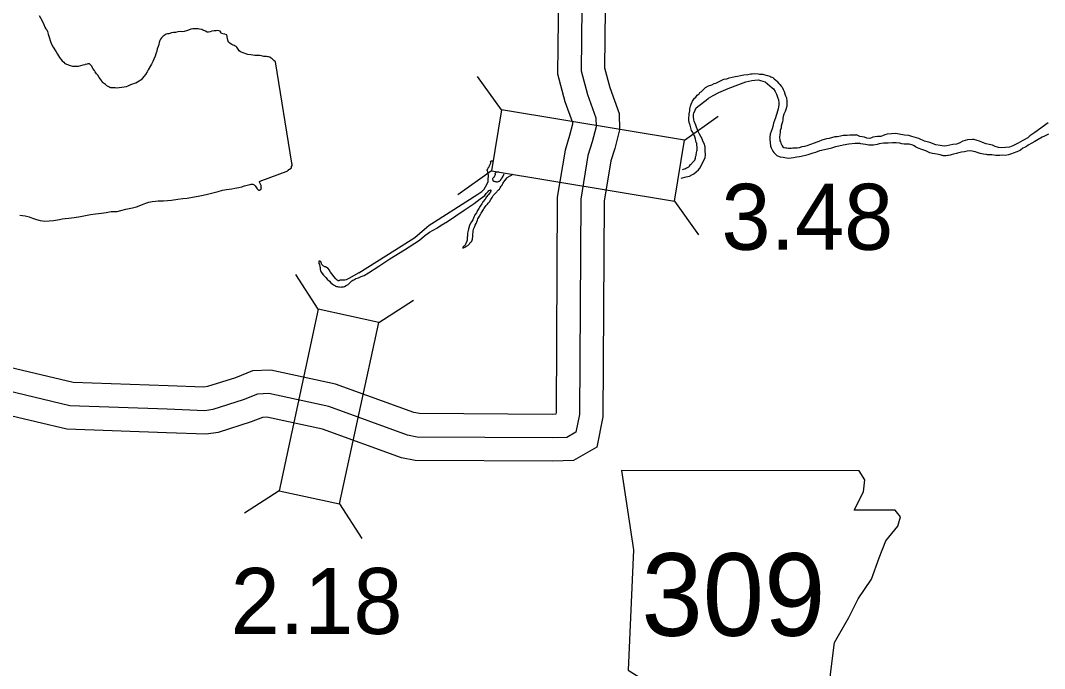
# Model space of a CAD drawing. Extents: x -83719 to 153526, y -11835 to 11446.
# Drawn here: x -4570.7 to -4352.2, y -30.4 to 107.8 of the extents above; entities that cross this region are included whole.
import ezdxf

# ---------------------------------------------------------------- set-up
doc = ezdxf.new("R2010")
doc.units = 0
for name, color, linetype in [('Level 10', 7, 'Continuous'), ('Level 20', 7, 'Continuous'), ('Level 21', 7, 'Continuous'), ('Level 25', 7, 'Continuous'), ('Level 58', 7, 'Continuous'), ('Level 59', 7, 'Continuous'), ('Level 9', 7, 'Continuous')]:
    doc.layers.add(name, color=color, linetype=linetype)

msp = doc.modelspace()

# ---------------------------------------------------------------- linework, layer by layer
at = {"layer": 'Level 10'}
for points in [[(-4455.75, 125.23), (-4456.06, 96.41), (-4454.48, 90.48), (-4452.86, 86.04), (-4452.85, 85.63), (-4453.48, 83.25), (-4454.45, 80.12), (-4456.11, 70.1), (-4456.37, 24.26), (-4456.46, 23.8), (-4457.21, 23.78), (-4485.53, 23.95), (-4486.75, 24.17), (-4503.46, 30.25), (-4517.26, 33.23), (-4521.18, 33.03), (-4524.8, 31.59), (-4530.76, 29.7), (-4531.56, 29.58), (-4539.13, 29.88), (-4559.44, 30.61), (-4572.91, 33.78)], [(-4445.78, 122.85), (-4446.05, 97.67), (-4444.93, 93.48), (-4442.91, 87.94), (-4442.82, 84.48), (-4443.86, 80.5), (-4444.69, 77.81), (-4446.11, 69.25), (-4446.37, 23.23), (-4447.68, 16.79), (-4452.68, 13.92), (-4457.08, 13.78), (-4486.46, 13.95), (-4489.38, 14.49), (-4506.24, 20.62), (-4518.07, 23.18), (-4519.02, 23.13), (-4521.43, 22.17), (-4528.49, 19.93), (-4531.01, 19.55), (-4539.51, 19.88), (-4560.78, 20.65), (-4573.96, 23.76)]]:
    msp.add_lwpolyline(points, dxfattribs=at)
at = {"layer": 'Level 20'}
for p, q in [((-4468.03, 88.71), (-4473.15, 95.86)), ((-4428.96, 82.25), (-4421.8, 87.37)), ((-4470.18, 75.68), (-4477.34, 70.56)), ((-4431.11, 69.22), (-4425.99, 62.07)), ((-4507.11, 46.18), (-4511.88, 53.58)), ((-4494.21, 43.39), (-4486.81, 48.16)), ((-4515.48, 7.47), (-4522.88, 2.71)), ((-4502.58, 4.68), (-4497.82, -2.71))]:
    msp.add_line(p, q, dxfattribs=at)
for points in [[(-4470.18, 75.68), (-4431.11, 69.22), (-4428.96, 82.25), (-4468.03, 88.71)], [(-4507.11, 46.18), (-4515.48, 7.47), (-4502.58, 4.68), (-4494.21, 43.39)]]:
    msp.add_lwpolyline(points, close=True, dxfattribs=at)
at = {"layer": 'Level 21'}
msp.add_lwpolyline([(-4442.39, 11.79), (-4439.85, -5.12), (-4440.98, -30.78), (-4438.73, -32.19), (-4434.5, -32.19), (-4434.5, -41.21), (-4398.97, -41.21), (-4397.28, -37.55), (-4397.84, -31.63), (-4396.99, -24.86), (-4393.89, -19.5), (-4391.92, -15.56), (-4389.1, -11.33), (-4387.41, -6.82), (-4386, -3.15), (-4383.46, -0.05), (-4382.9, 1.93), (-4384.02, 3.34), (-4392.77, 3.34), (-4390.79, 7.28), (-4390.51, 9.82), (-4391.68, 11.77)], close=True, dxfattribs=at)
at = {"layer": 'Level 59'}
msp.add_lwpolyline([(-4450.76, 124.04), (-4451.05, 97.04), (-4449.7, 91.98), (-4447.89, 86.99), (-4447.83, 85.06), (-4448.67, 81.88), (-4449.57, 78.97), (-4451.11, 69.67), (-4451.37, 23.74), (-4452.13, 20), (-4454.08, 18.88), (-4457.15, 18.78), (-4486, 18.95), (-4488.06, 19.33), (-4504.85, 25.43), (-4517.67, 28.2), (-4520.1, 28.08), (-4523.12, 26.88), (-4529.62, 24.81), (-4531.29, 24.56), (-4539.32, 24.88), (-4560.11, 25.63), (-4573.43, 28.77)], dxfattribs=at)
at = {"layer": 'Level 9'}
for points in [[(-4566.66, 108.87), (-4566.05, 107.71), (-4565.64, 106.95), (-4565.47, 106.38), (-4565.23, 106.02), (-4565.03, 105.75), (-4564.89, 105.45), (-4564.72, 104.82), (-4564.51, 104.22), (-4564.27, 103.32), (-4564, 102.69), (-4563.69, 102.06), (-4563.05, 101.1), (-4562.74, 100.6), (-4562.34, 99.91), (-4561.73, 99.18), (-4561.43, 98.85), (-4561.16, 98.58), (-4560.05, 98.19), (-4559.55, 98.06), (-4558.69, 98.01), (-4558.29, 98.04), (-4557.79, 98.15), (-4557.26, 98.29), (-4556.86, 98.39), (-4556.76, 98.43), (-4556.36, 98.5)], [(-4528.08, 105.46), (-4528.32, 105.59), (-4528.59, 105.62), (-4528.89, 105.59), (-4529.35, 105.55), (-4529.82, 105.48), (-4530.18, 105.37), (-4530.51, 105.27), (-4530.65, 105.27), (-4530.81, 105.3), (-4531.18, 105.5), (-4531.32, 105.56), (-4531.75, 105.73), (-4531.99, 105.86), (-4532.49, 105.92), (-4532.72, 105.98), (-4533.05, 105.98), (-4533.49, 105.97), (-4533.85, 106), (-4534.32, 105.93), (-4534.78, 105.69), (-4535.21, 105.59), (-4535.75, 105.42), (-4536.11, 105.38), (-4536.61, 105.41), (-4537.08, 105.37), (-4537.61, 105.23), (-4537.78, 105.23), (-4538.01, 105.23), (-4538.44, 105.16), (-4538.97, 104.95), (-4539.27, 104.91), (-4539.6, 104.84), (-4539.8, 104.71), (-4540.03, 104.54), (-4540.23, 104.4), (-4540.53, 104.07), (-4540.76, 103.8), (-4540.89, 103.53), (-4541.05, 103.06), (-4541.15, 102.66), (-4541.24, 102.19), (-4541.47, 101.72), (-4541.57, 101.25), (-4541.76, 100.65), (-4541.92, 100.15), (-4542.18, 99.54), (-4542.38, 99.04), (-4542.67, 98.47), (-4542.9, 98.07), (-4543.42, 97.26), (-4543.65, 96.79), (-4544.01, 96.22), (-4544.34, 95.82), (-4544.6, 95.45), (-4544.9, 95.14), (-4545.33, 94.81), (-4545.69, 94.6), (-4546.03, 94.43), (-4546.39, 94.33), (-4546.76, 94.16), (-4547.15, 94.02), (-4547.45, 93.92), (-4547.65, 93.81), (-4547.75, 93.78)], [(-4519.64, 71.61), (-4519.41, 71.71), (-4519.35, 71.74), (-4519.25, 71.98), (-4519.28, 72.18), (-4519.32, 72.24), (-4519.29, 72.48), (-4519.32, 72.58), (-4519.42, 72.84), (-4519.49, 72.98), (-4519.66, 73.27), (-4519.63, 73.41), (-4519.2, 73.65), (-4519.17, 73.65), (-4513.96, 75.57), (-4513.76, 75.67), (-4513.56, 75.84), (-4513.49, 75.87), (-4513.36, 75.98), (-4513.23, 76.08), (-4512.93, 76.25), (-4512.83, 76.52), (-4512.8, 76.62), (-4512.7, 76.88), (-4512.71, 77.08), (-4512.74, 77.25), (-4512.77, 77.32), (-4512.77, 77.38), (-4516.26, 98.98), (-4516.63, 99.27), (-4516.66, 99.34), (-4516.9, 99.54), (-4516.9, 99.57), (-4517, 99.64), (-4517.13, 99.73), (-4517.27, 99.87), (-4517.37, 99.9), (-4517.44, 99.93), (-4517.7, 100), (-4517.87, 100.03), (-4518.14, 100.06), (-4518.74, 100.12), (-4519.24, 100.21), (-4519.6, 100.28), (-4520.1, 100.27), (-4520.44, 100.3), (-4520.67, 100.33), (-4521.07, 100.36), (-4521.47, 100.42), (-4522.14, 100.55), (-4522.57, 100.68), (-4522.91, 100.78), (-4523.38, 100.94), (-4523.74, 101.07), (-4524.01, 101.33), (-4524.22, 101.66), (-4524.52, 102.06), (-4524.62, 102.19), (-4524.86, 102.32), (-4525.06, 102.42), (-4525.29, 102.52), (-4525.59, 102.62), (-4525.93, 102.88), (-4526.26, 103.18), (-4526.43, 103.61), (-4526.47, 103.91), (-4526.64, 104.68), (-4526.71, 104.74), (-4527.05, 104.87), (-4527.15, 104.87), (-4527.51, 104.93), (-4527.78, 105.03), (-4527.85, 105.16), (-4528.08, 105.46)], [(-4556.01, 98.51), (-4556.36, 98.5)], [(-4554.88, 97.08), (-4555.18, 97.51), (-4555.32, 97.71), (-4555.46, 98.01), (-4555.66, 98.24), (-4555.86, 98.47), (-4555.96, 98.5), (-4556.01, 98.51)], [(-4553.36, 94.99), (-4553.58, 95.23), (-4553.83, 95.61), (-4554.15, 96.11), (-4554.45, 96.43), (-4554.7, 96.8), (-4554.88, 97.08)], [(-4420.57, 95.24), (-4419.97, 95.35), (-4419.44, 95.53), (-4418.78, 95.71), (-4418.15, 95.82), (-4417.69, 95.93), (-4417.05, 96.04), (-4416.29, 96.19), (-4415.49, 96.28), (-4415.16, 96.35), (-4414.83, 96.39), (-4414.53, 96.43), (-4413.97, 96.44), (-4413.23, 96.39), (-4412.96, 96.36), (-4412.27, 96.34), (-4411.83, 96.21), (-4411.26, 96.06), (-4410.79, 95.87), (-4410.52, 95.74), (-4410.15, 95.58), (-4409.85, 95.35), (-4409.51, 95.03), (-4409.24, 94.83), (-4408.86, 94.34), (-4408.66, 94.11), (-4408.35, 93.78), (-4408.11, 93.52), (-4407.91, 93.09), (-4407.73, 92.63), (-4407.55, 92.13), (-4407.45, 91.73), (-4407.2, 91.3), (-4407.12, 90.57), (-4407.11, 89.94), (-4407.17, 89.47), (-4407.35, 88.8), (-4407.48, 88.39), (-4407.77, 87.79), (-4407.89, 87.32), (-4407.98, 86.95), (-4407.98, 86.62), (-4408.04, 86.15), (-4408.19, 85.71), (-4408.32, 85.21), (-4408.38, 84.91), (-4408.44, 84.7), (-4408.53, 84.3), (-4408.59, 83.97), (-4408.65, 83.4), (-4408.67, 82.93), (-4408.62, 82.13), (-4408.52, 81.93), (-4408.41, 81.64), (-4408.31, 81.3), (-4408.13, 81.04), (-4408, 80.84), (-4407.76, 80.71), (-4407.33, 80.62), (-4407.13, 80.59), (-4406.76, 80.57), (-4406.39, 80.57), (-4406.23, 80.58), (-4405.86, 80.59), (-4405.63, 80.59), (-4404.96, 80.6), (-4404.47, 80.71), (-4403.87, 80.89), (-4403.31, 81), (-4402.81, 81.11), (-4402.05, 81.4), (-4401.22, 81.68), (-4400.66, 81.92), (-4400.23, 82.07), (-4399.57, 82.31), (-4398.57, 82.6), (-4398.01, 82.71), (-4396.85, 83), (-4396.35, 83.04), (-4395.66, 83.19), (-4395.09, 83.3), (-4394.26, 83.35), (-4393.69, 83.4), (-4393.3, 83.4), (-4392.73, 83.38), (-4392.56, 83.39), (-4392.36, 83.41)], [(-4550.94, 93.41), (-4551.34, 93.44), (-4551.58, 93.51), (-4551.81, 93.6), (-4552.22, 93.87), (-4552.52, 94.1), (-4552.75, 94.23), (-4552.95, 94.43), (-4553.09, 94.56), (-4553.29, 94.86), (-4553.36, 94.99)], [(-4429.39, 76.03), (-4428.79, 76.19), (-4428.56, 76.33), (-4428.33, 76.43), (-4428.06, 76.54), (-4427.93, 76.71), (-4427.67, 77.05), (-4427.57, 77.15), (-4427.44, 77.25), (-4427.35, 77.39), (-4427.02, 77.73), (-4426.95, 77.8), (-4426.79, 78), (-4426.6, 78.4), (-4426.6, 78.67), (-4426.51, 78.97), (-4426.51, 79.17), (-4426.42, 79.47), (-4426.39, 79.64), (-4426.36, 79.88), (-4426.27, 80.11), (-4426.24, 80.41), (-4426.24, 80.61), (-4426.25, 80.81), (-4426.32, 81.21), (-4426.36, 81.61), (-4426.47, 81.78), (-4426.54, 82.18), (-4426.61, 82.44), (-4426.76, 82.97), (-4426.79, 83.1), (-4426.96, 83.37), (-4427.14, 83.73), (-4427.28, 84), (-4427.45, 84.33), (-4427.63, 84.86), (-4427.77, 85.42), (-4427.95, 86.05), (-4428.02, 86.55), (-4428.06, 86.85), (-4427.98, 87.69), (-4427.98, 87.89), (-4427.86, 88.52), (-4427.84, 88.96), (-4427.68, 89.53), (-4427.53, 89.96), (-4427.24, 90.57), (-4426.95, 91.01), (-4426.82, 91.21), (-4426.59, 91.45), (-4426.26, 91.82), (-4425.87, 92.16), (-4425.68, 92.4), (-4425.41, 92.57), (-4425.09, 92.91), (-4424.82, 93.12), (-4424.46, 93.46), (-4423.87, 93.84), (-4423.14, 94.05), (-4422.65, 94.3), (-4422.29, 94.44), (-4421.69, 94.72), (-4421.16, 94.96), (-4420.57, 95.24)], [(-4425.04, 82.07), (-4425.22, 82.54), (-4425.52, 83.03), (-4425.8, 83.56), (-4426.04, 84.09), (-4426.43, 85.01), (-4426.57, 85.48), (-4426.89, 86.31), (-4426.96, 86.57), (-4427.07, 87.2), (-4427.08, 87.7), (-4426.96, 88.04), (-4426.73, 88.68), (-4426.48, 89.12), (-4424.9, 90.35), (-4424.34, 90.79), (-4423.85, 91.2), (-4422.83, 91.79), (-4421.65, 92.38), (-4419.66, 93.26), (-4417.61, 94.03), (-4415.86, 94.67), (-4414.6, 94.96), (-4413.94, 95.04), (-4413.21, 95.09), (-4412.74, 95), (-4411.77, 94.68), (-4411.26, 94.26), (-4410.78, 93.83), (-4410.24, 93.44), (-4409.97, 93.18), (-4409.63, 92.66), (-4409.32, 92.06), (-4409.14, 91.43), (-4408.93, 90.83), (-4408.82, 90.27), (-4408.84, 89.7), (-4408.9, 89.33), (-4408.99, 88.93), (-4409.15, 88.46), (-4409.27, 87.96), (-4409.43, 87.49), (-4409.55, 87.02), (-4409.96, 85.88), (-4410.15, 85.17), (-4410.3, 84.67), (-4410.72, 83.56), (-4410.77, 82.92), (-4410.79, 82.39), (-4410.71, 81.72), (-4410.63, 80.96), (-4410.49, 80.63), (-4410.14, 79.9), (-4409.94, 79.64), (-4409.57, 79.28), (-4409.29, 78.98), (-4409.16, 78.88), (-4408.59, 78.73), (-4407.92, 78.61), (-4407.22, 78.49), (-4406.88, 78.43), (-4406.22, 78.48), (-4405.72, 78.55), (-4405.02, 78.67), (-4404.43, 78.78), (-4403.43, 79), (-4402.57, 79.22), (-4401.51, 79.54), (-4400.98, 79.71), (-4400.12, 80.03), (-4399.13, 80.29), (-4397.57, 80.62), (-4396.71, 80.87), (-4395.12, 81.23), (-4393.92, 81.46), (-4392.56, 81.62), (-4391.69, 81.6)], [(-4547.75, 93.78), (-4548.07, 93.64), (-4548.54, 93.56), (-4549.06, 93.48), (-4549.58, 93.38), (-4550.15, 93.31), (-4550.47, 93.38), (-4550.94, 93.41)], [(-4351.37, 85.98), (-4354.22, 83.87), (-4355.28, 83.16), (-4355.74, 82.76), (-4356.8, 82.18), (-4357.76, 81.6), (-4358.93, 81.05), (-4359.62, 80.77), (-4361.32, 80.62), (-4361.99, 80.71), (-4362.66, 80.87), (-4363.27, 81.2), (-4364, 81.32), (-4364.6, 81.48), (-4365.38, 81.74), (-4366.05, 82.03), (-4366.52, 82.19), (-4367.22, 82.38), (-4367.52, 82.38), (-4368.62, 82.33), (-4369.58, 82.02), (-4370.38, 81.64), (-4370.95, 81.4), (-4371.75, 81.33), (-4373.01, 81.01), (-4373.58, 80.94), (-4374.45, 81.09), (-4375.38, 81.28), (-4376.62, 81.73), (-4377.8, 82.05), (-4378.94, 82.64), (-4380.44, 83.05), (-4381.11, 83.25), (-4382.05, 83.34), (-4383.19, 83.52), (-4383.86, 83.65), (-4384.82, 83.6), (-4385.72, 83.52), (-4386.22, 83.42), (-4386.75, 83.14), (-4387.05, 83.04), (-4387.79, 83.03), (-4388.29, 82.96), (-4388.79, 82.92), (-4389.05, 82.78)], [(-4389.05, 82.78), (-4389.45, 82.63), (-4390.07, 82.66), (-4390.54, 82.86), (-4391.56, 83.03), (-4392.13, 83.32), (-4392.36, 83.41)], [(-4351.34, 83.51), (-4352.17, 83.13), (-4352.67, 82.86), (-4353.53, 82.42), (-4354.23, 81.97), (-4354.86, 81.63), (-4355.66, 81.19), (-4356.02, 80.88), (-4356.42, 80.68), (-4356.75, 80.51), (-4357.25, 80.13), (-4357.68, 79.9), (-4358.04, 79.76), (-4358.84, 79.45), (-4359.21, 79.31), (-4359.87, 79.1), (-4360.47, 78.96), (-4361.14, 79.02), (-4361.71, 78.98), (-4362.57, 79), (-4363.38, 79.09), (-4363.78, 79.12), (-4364.31, 79.15), (-4364.51, 79.21), (-4365.18, 79.3), (-4365.52, 79.37), (-4365.92, 79.39), (-4366.28, 79.52), (-4366.55, 79.65), (-4366.89, 79.75), (-4367.02, 79.75), (-4367.62, 79.91), (-4367.96, 79.97), (-4368.63, 79.9), (-4369.23, 79.79), (-4369.86, 79.71), (-4370.19, 79.61), (-4370.69, 79.47), (-4370.96, 79.43), (-4371.59, 79.26), (-4372.09, 79.09), (-4372.32, 79.02), (-4372.62, 79.01), (-4372.69, 78.98), (-4372.82, 78.98), (-4373.12, 78.94), (-4373.25, 78.94), (-4373.35, 78.9), (-4373.59, 78.93), (-4373.69, 78.93), (-4373.96, 78.96), (-4374.02, 79), (-4374.42, 79.09), (-4374.42, 79.12), (-4374.79, 79.19), (-4375.56, 79.34), (-4376.06, 79.44), (-4376.33, 79.47), (-4376.63, 79.53), (-4377.51, 79.99), (-4378.31, 80.28), (-4379.15, 80.53), (-4379.72, 80.83), (-4379.95, 81.06), (-4380.26, 81.19), (-4380.72, 81.32), (-4381.03, 81.38), (-4382.09, 81.43), (-4382.6, 81.49), (-4383.03, 81.62), (-4383.8, 81.71), (-4384.57, 81.67), (-4385.5, 81.59), (-4385.94, 81.62), (-4386.54, 81.58), (-4387.46, 81.45)], [(-4429.72, 74.14), (-4428.65, 74.43), (-4427.92, 74.61), (-4427.3, 74.92), (-4426.97, 75.09), (-4426.02, 75.91), (-4425.69, 76.29), (-4424.82, 77.91), (-4424.54, 78.54), (-4424.52, 79.11), (-4424.57, 80.08), (-4424.58, 80.61), (-4424.58, 80.81), (-4424.8, 81.51), (-4425.04, 82.07)], [(-4387.46, 81.45), (-4387.86, 81.31), (-4388.62, 81.21), (-4389.61, 81.21), (-4390.37, 81.31), (-4391.33, 81.5), (-4391.69, 81.6)], [(-4498.45, 53.98), (-4490.79, 58.81), (-4486.51, 61.49), (-4483.92, 63.71), (-4483.43, 64.16), (-4482.31, 64.85), (-4473.07, 70.77), (-4472.22, 71.32), (-4471.73, 71.8), (-4471.4, 72.31), (-4470.89, 73.35), (-4470.87, 73.68), (-4470.84, 74.09), (-4470.81, 74.42), (-4470.79, 74.82), (-4470.83, 75.12), (-4470.9, 75.42), (-4470.93, 75.52), (-4471, 75.62), (-4471.04, 75.68), (-4471.07, 75.78), (-4471.11, 75.85), (-4471.11, 75.88), (-4471.08, 75.98), (-4471.04, 76.02), (-4470.95, 76.15), (-4470.88, 76.25), (-4470.85, 76.32), (-4470.79, 76.42), (-4470.75, 76.49), (-4470.66, 76.56), (-4470.66, 76.62), (-4470.56, 76.79), (-4470.5, 76.96), (-4470.43, 77.1), (-4470.4, 77.2), (-4470.31, 77.43), (-4470.31, 77.53), (-4470.34, 77.67), (-4470.31, 77.77), (-4470.25, 77.8), (-4470.18, 77.84), (-4470.15, 77.84), (-4470.12, 77.87), (-4469.95, 77.84), (-4469.9, 77.83)], [(-4470.61, 69.12), (-4470.32, 69.59), (-4470.03, 70.03), (-4469.96, 70.17), (-4469.77, 70.47), (-4469.51, 70.74), (-4469.28, 70.95), (-4469.05, 71.22), (-4468.92, 71.35), (-4468.86, 71.42), (-4468.66, 71.69), (-4468.46, 71.8), (-4468.3, 72.07), (-4468.08, 72.41), (-4467.91, 72.64), (-4467.79, 72.84), (-4467.72, 72.98), (-4467.59, 73.22), (-4467.53, 73.35), (-4467.24, 73.69), (-4467.2, 73.72), (-4467.14, 73.76), (-4466.91, 74.16), (-4466.81, 74.3), (-4465.56, 74.97)], [(-4469.36, 75.03), (-4469.36, 75.02), (-4469.36, 74.85), (-4469.48, 74.58), (-4469.48, 74.55), (-4469.55, 74.41), (-4469.58, 74.34), (-4469.71, 74.27), (-4469.81, 74.21), (-4469.87, 74.1), (-4469.91, 74.04), (-4469.94, 73.97), (-4469.94, 73.9), (-4469.9, 73.8), (-4469.9, 73.74), (-4469.87, 73.69)], [(-4469.36, 75.03), (-4469.35, 75.13), (-4469.33, 75.23), (-4469.3, 75.29), (-4469.16, 75.41), (-4468.99, 75.47), (-4468.87, 75.5), (-4468.69, 75.58), (-4468.65, 75.6)], [(-4468.13, 73.83), (-4468.08, 74.04), (-4467.91, 74.24), (-4467.69, 74.58), (-4467.49, 74.92), (-4467.45, 75.09)], [(-4531.69, 70.55), (-4530.76, 70.76), (-4528.47, 71.32), (-4527.57, 71.56), (-4526.67, 71.7), (-4525.54, 71.88), (-4524.91, 72.02), (-4524.05, 72.19), (-4523.45, 72.33), (-4522.82, 72.51), (-4522.29, 72.65), (-4521.99, 72.72), (-4521.62, 72.82), (-4521.42, 72.86), (-4521.26, 72.89), (-4521.09, 72.89), (-4520.79, 72.7), (-4520.59, 72.53), (-4520.56, 72.48)], [(-4520.56, 72.48), (-4520.46, 72.3), (-4520.29, 72.12), (-4520.14, 71.85), (-4519.96, 71.65), (-4519.85, 71.6), (-4519.64, 71.61)], [(-4469.87, 73.69), (-4469.84, 73.65), (-4469.78, 73.6), (-4469.71, 73.54), (-4469.6, 73.5)], [(-4469.6, 73.5), (-4469.43, 73.45), (-4469.26, 73.42), (-4469.09, 73.39), (-4468.99, 73.39), (-4468.9, 73.39), (-4468.64, 73.42)], [(-4468.13, 73.83), (-4468.16, 73.77), (-4468.21, 73.7), (-4468.29, 73.62), (-4468.43, 73.5), (-4468.54, 73.45), (-4468.64, 73.42)], [(-4570.79, 66.24), (-4570.25, 66.18), (-4569.68, 66.09), (-4568.82, 65.9), (-4568.08, 65.64), (-4567.24, 65.31), (-4566.48, 65.12), (-4565.48, 65), (-4564.54, 65.04), (-4563.58, 65.11), (-4562.35, 65.33), (-4561.78, 65.47), (-4561.09, 65.54), (-4560.32, 65.62), (-4559.22, 65.76), (-4557.86, 66.01), (-4556.76, 66.22), (-4555.7, 66.43), (-4554.67, 66.57), (-4553.37, 66.72), (-4552.34, 66.83), (-4551.27, 67.04), (-4550.04, 67.02), (-4549.24, 67.23), (-4548.15, 67.51), (-4546.72, 67.79), (-4545.92, 68.07), (-4545.32, 68.24), (-4544.46, 68.58), (-4543.7, 68.92), (-4543.3, 69.06), (-4542.54, 69.17), (-4541.84, 69.21), (-4541.3, 69.28), (-4540.14, 69.33), (-4539.27, 69.4), (-4538.44, 69.48), (-4537.11, 69.69), (-4535.98, 69.84), (-4535.08, 69.91), (-4533.92, 70.12), (-4532.75, 70.3), (-4531.69, 70.55)], [(-4484.42, 61.87), (-4483.37, 62.62), (-4481.82, 63.46), (-4480.9, 64.11), (-4479.55, 64.94), (-4475.97, 67.34), (-4473.83, 68.75), (-4472.55, 69.71), (-4471.57, 70.47), (-4471.28, 70.87), (-4471.08, 71.08), (-4470.89, 71.28), (-4470.69, 71.49), (-4470.66, 71.49), (-4470.52, 71.59), (-4470.43, 71.62), (-4470.39, 71.63), (-4470.36, 71.63), (-4470.29, 71.59), (-4470.29, 71.56), (-4470.29, 71.53), (-4470.29, 71.39), (-4470.35, 71.29), (-4470.38, 71.19), (-4470.48, 70.99), (-4470.77, 70.68), (-4470.94, 70.51), (-4471.2, 70.14), (-4471.52, 69.67), (-4471.97, 69.09), (-4472.23, 68.65), (-4472.59, 68.18), (-4472.88, 67.71), (-4473.17, 67.23), (-4473.36, 66.79), (-4473.69, 66.35), (-4473.78, 66.12), (-4473.91, 65.82), (-4474.16, 65.24), (-4474.42, 64.84), (-4474.62, 64.53), (-4474.87, 64.06), (-4474.96, 63.59), (-4475.06, 63.32), (-4475.12, 62.99), (-4475.21, 62.72), (-4475.27, 62.39), (-4475.3, 62.15), (-4475.3, 61.88), (-4475.29, 61.75), (-4475.32, 61.55), (-4475.32, 61.28), (-4475.38, 60.95), (-4475.41, 60.68), (-4475.53, 60.35), (-4475.63, 60.18), (-4475.73, 60.04), (-4475.85, 59.81), (-4475.95, 59.7), (-4476.08, 59.63), (-4476.22, 59.5), (-4476.25, 59.4), (-4476.25, 59.36), (-4476.28, 59.23), (-4476.14, 59.3), (-4475.82, 59.47), (-4475.62, 59.61), (-4475.49, 59.65), (-4475.19, 59.82), (-4475.06, 59.95), (-4474.86, 60.16), (-4474.67, 60.4), (-4474.5, 60.57), (-4474.37, 60.74), (-4474.28, 60.9), (-4474.18, 61.14), (-4474.19, 61.41), (-4474.16, 61.54), (-4474.13, 62.01), (-4474.14, 62.31), (-4474.08, 62.58), (-4474.05, 62.88), (-4473.96, 63.25), (-4473.8, 63.72), (-4473.64, 64.12), (-4473.45, 64.49), (-4473.29, 64.86), (-4473.16, 65.2), (-4473.04, 65.5), (-4472.91, 65.7), (-4472.71, 66.07), (-4472.46, 66.51), (-4472.33, 66.68), (-4471.88, 67.46), (-4471.78, 67.59), (-4471.68, 67.8), (-4471.52, 68.03), (-4471.29, 68.34), (-4471, 68.61), (-4470.84, 68.81), (-4470.61, 69.12)], [(-4499.72, 52.42), (-4499.56, 52.49), (-4499.09, 52.74), (-4498.8, 52.81), (-4498.56, 52.88), (-4497.94, 53.19), (-4497.34, 53.4), (-4496.39, 53.99), (-4494.22, 55.37), (-4491.82, 56.95), (-4488.69, 58.85), (-4485.53, 60.91), (-4484.42, 61.87)], [(-4506.86, 56.48), (-4506.89, 56.5), (-4506.95, 56.48), (-4506.98, 56.45), (-4507, 56.39), (-4507.01, 56.3), (-4507.01, 56.18), (-4506.99, 56.12)], [(-4506.99, 56.12), (-4506.99, 56.05), (-4506.98, 55.95), (-4506.88, 55.72), (-4506.84, 55.62), (-4506.81, 55.48), (-4506.8, 55.32), (-4506.73, 55.12), (-4506.73, 54.99), (-4506.69, 54.72), (-4506.69, 54.65), (-4506.66, 54.55), (-4506.62, 54.42), (-4506.55, 54.32), (-4506.55, 54.22), (-4506.51, 54.12), (-4505.97, 53.5), (-4505.53, 52.97), (-4505.25, 52.61), (-4504.74, 52.16), (-4504.41, 51.86), (-4504.13, 51.63), (-4503.97, 51.47), (-4503.76, 51.34), (-4503.7, 51.31), (-4503.59, 51.24), (-4503.43, 51.15), (-4503.36, 51.12), (-4503.22, 51.05), (-4503.12, 51.02), (-4502.99, 51.02), (-4502.79, 50.99), (-4502.62, 51), (-4502.59, 50.96), (-4502.26, 50.94), (-4502.12, 50.97), (-4501.72, 51.01), (-4501.53, 51.05), (-4501.16, 51.26), (-4500.74, 51.5), (-4500.34, 51.89)], [(-4503.46, 52.72), (-4504.52, 54.13), (-4504.79, 54.59), (-4505.03, 54.92), (-4505.37, 55.08), (-4505.57, 55.21), (-4505.77, 55.27), (-4505.91, 55.37), (-4506.04, 55.43), (-4506.11, 55.53), (-4506.21, 55.6), (-4506.35, 55.73), (-4506.42, 55.89), (-4506.45, 55.99), (-4506.49, 56.09), (-4506.52, 56.26), (-4506.63, 56.36), (-4506.69, 56.42), (-4506.73, 56.42), (-4506.86, 56.48), (-4506.86, 56.48)], [(-4503.46, 52.72), (-4503.41, 52.66), (-4503.33, 52.6), (-4503.21, 52.54), (-4503.08, 52.44), (-4502.86, 52.36), (-4502.68, 52.34), (-4502.5, 52.38)], [(-4498.45, 53.98), (-4500.59, 52.77), (-4501.19, 52.46), (-4501.45, 52.42), (-4501.65, 52.38), (-4501.72, 52.38), (-4501.88, 52.38), (-4501.92, 52.38), (-4501.98, 52.38), (-4502.18, 52.37), (-4502.32, 52.37), (-4502.45, 52.37), (-4502.5, 52.38)], [(-4500.34, 51.89), (-4500.25, 51.98), (-4500.1, 52.13), (-4499.93, 52.25), (-4499.72, 52.42)]]:
    msp.add_lwpolyline(points, dxfattribs=at)

# ---------------------------------------------------------------- texts
at = {"layer": 'Level 21'}
msp.add_text('309', height=17.6, dxfattribs=at).set_placement((-4438.17, -23.43))
at = {"layer": 'Level 25'}
msp.add_text('3.48', height=14.08, dxfattribs=at).set_placement((-4421.09, 58.87))
at = {"layer": 'Level 58'}
for s, p in [('3.48', (-4421.09, 58.87)), ('2.18', (-4525.8, -23.05))]:
    msp.add_text(s, height=14.08, dxfattribs=at).set_placement(p)

doc.saveas('drawing.dxf')
